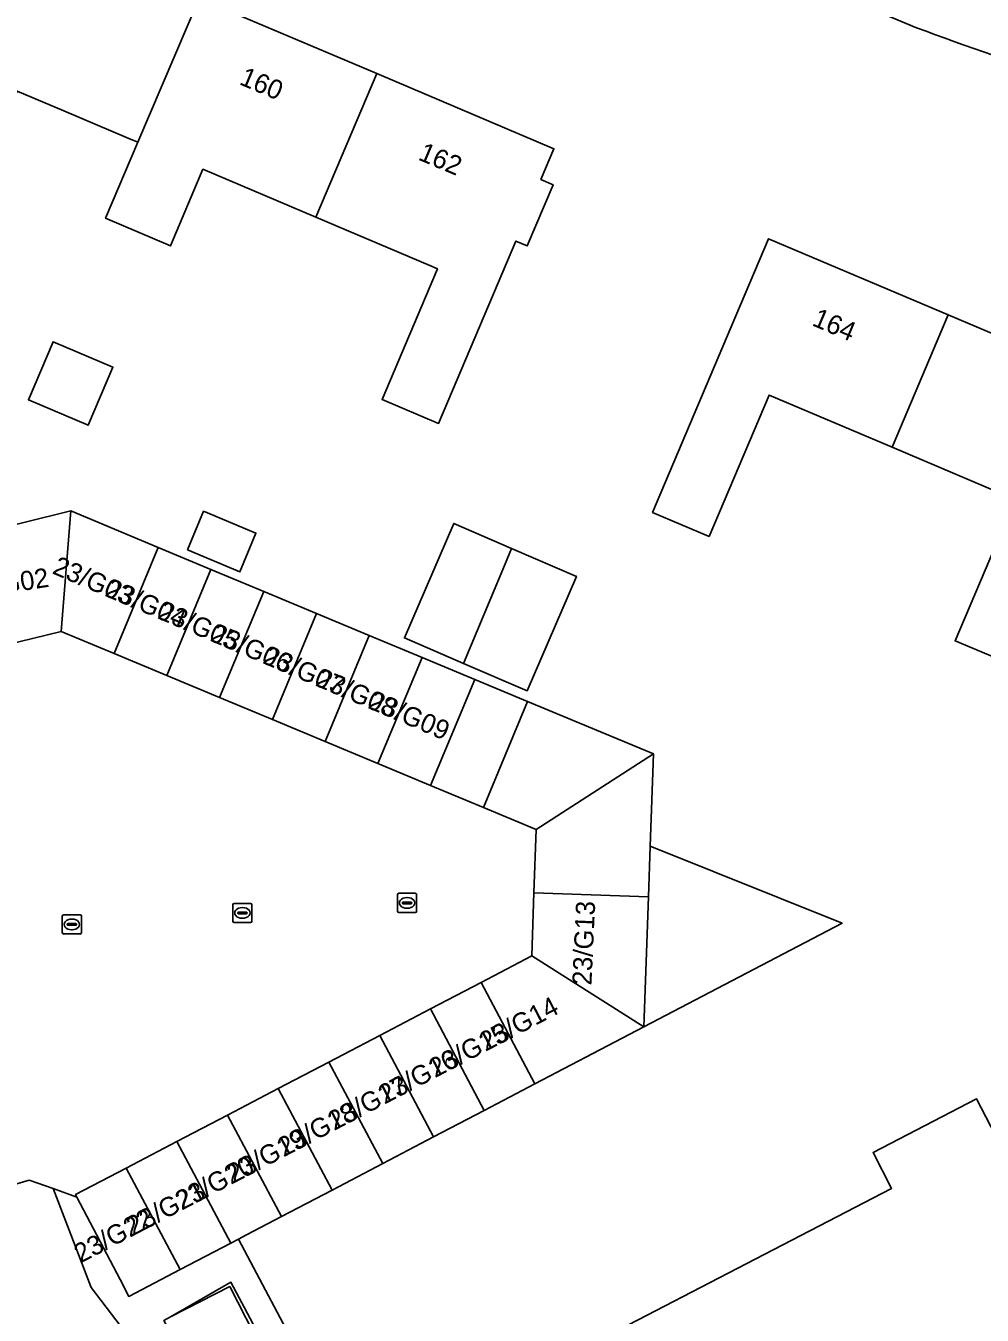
# Model space of a CAD drawing. Extents: x 162073 to 163043, y 381818 to 382561.
# Drawn here: x 162517.9 to 162567.8, y 382402.1 to 382469.3 of the extents above; entities that cross this region are included whole.
import ezdxf

# ---------------------------------------------------------------- set-up
doc = ezdxf.new("R2010")
doc.units = 0
for name, color, linetype in [('IMGEO_Erf', 7, 'Continuous'), ('IMGEO_Kolk', 7, 'Continuous'), ('IMGEO_Pand', 7, 'Continuous'), ('IMGEO_Pand_nummerreeks', 7, 'Continuous'), ('IMGEO_Rijbaan_lokaal_open', 7, 'Continuous'), ('IMGEO_Voetpad_open', 7, 'Continuous')]:
    doc.layers.add(name, color=color, linetype=linetype)

msp = doc.modelspace()

# ---------------------------------------------------------------- linework, layer by layer
at = {"layer": 'IMGEO_Erf'}
for points in [[(162564.361, 382469.237), (162500, 382496.185)], [(162526.962, 382470.776), (162536.214, 382466.853), (162545.458, 382462.933), (162544.778, 382461.328), (162545.416, 382461.057), (162544.064, 382457.868), (162543.471, 382458.119), (162539.438, 382448.608), (162536.492, 382449.857), (162539.383, 382456.674), (162538.978, 382456.846), (162533.041, 382459.363), (162527.152, 382461.86), (162525.471, 382457.865), (162522.077, 382459.304), (162523.766, 382463.272), (162523.294, 382463.472), (162519.902, 382464.91), (162517.475, 382465.939), (162517.154, 382465.181), (162513.979, 382466.527), (162515.504, 382470.123)], [(162515.42, 382442.864), (162520.267, 382444.049), (162524.823, 382442.149), (162527.574, 382441.002), (162530.326, 382439.854), (162533.078, 382438.707), (162535.83, 382437.56), (162538.581, 382436.412), (162541.333, 382435.265), (162544.085, 382434.117), (162550.649, 382431.38), (162550.479, 382426.575), (162560.476, 382422.56), (162550.145, 382417.154), (162544.462, 382414.18), (162541.819, 382412.797), (162539.176, 382411.414), (162536.533, 382410.031), (162533.89, 382408.649), (162531.247, 382407.266), (162529.419, 382406.309), (162529.011, 382406.096), (162569.932, 382328.823)], [(162570.821, 382350.911), (162559.051, 382373.589), (162560.496, 382374.339), (162558.734, 382377.733), (162557.289, 382376.983), (162555.051, 382375.822), (162551.058, 382383.517), (162553.32, 382384.692), (162545.561, 382399.659), (162563.063, 382408.737), (162562.093, 382410.607), (162567.488, 382413.404), (162568.456, 382411.534)], [(162523.393, 382400.86), (162521.332, 382403.562), (162519.34, 382408.727), (162518.098, 382409.172), (162513.191, 382407.718), (162515.105, 382401.997)], [(162531.06, 382399.243), (162528.612, 382403.839), (162525.466, 382402.043), (162528.556, 382403.617), (162529.802, 382401.169)]]:
    msp.add_lwpolyline(points, dxfattribs=at)
for points in [[(162574.703, 382448.738), (162575.327, 382448.474), (162573.959, 382445.247), (162573.328, 382445.514), (162569.311, 382436.041), (162566.374, 382437.286), (162569.496, 382444.651), (162563.083, 382447.37), (162556.671, 382450.088), (162553.548, 382442.722), (162550.601, 382443.971), (162554.7, 382453.638), (162556.651, 382458.241), (162566.01, 382454.273), (162575.368, 382450.305)], [(162518.056, 382449.845), (162519.344, 382452.87), (162522.461, 382451.542), (162521.173, 382448.518)], [(162526.347, 382442.014), (162527.188, 382444.031), (162529.921, 382442.891), (162529.08, 382440.874)], [(162544.057, 382434.671), (162540.749, 382436.096), (162537.663, 382437.426), (162540.235, 382443.395), (162543.246, 382442.097), (162546.629, 382440.64)]]:
    msp.add_lwpolyline(points, close=True, dxfattribs=at)
msp.add_arc((162613.108, 382599.454), 139.042, 249.47654, 256.46221, dxfattribs=at)
at = {"layer": 'IMGEO_Kolk'}
for p, q in [((162528.712, 382422.667), (162528.712, 382423.519)), ((162528.787, 382423.593), (162529.639, 382423.593)), ((162529.713, 382423.519), (162529.713, 382422.667)), ((162537.298, 382423.19), (162537.298, 382424.042)), ((162537.373, 382424.116), (162538.225, 382424.116)), ((162537.557, 382423.61), (162537.557, 382423.622)), ((162537.995, 382423.573), (162537.597, 382423.573)), ((162537.6, 382423.659), (162537.998, 382423.659)), ((162537.786, 382423.896), (162537.811, 382423.896)), ((162538.041, 382423.622), (162538.041, 382423.61)), ((162538.299, 382424.042), (162538.299, 382423.19)), ((162519.82, 382422.07), (162519.82, 382422.922)), ((162519.895, 382422.996), (162520.747, 382422.996)), ((162520.821, 382422.922), (162520.821, 382422.07)), ((162528.971, 382423.087), (162528.971, 382423.099)), ((162529.409, 382423.05), (162529.011, 382423.05)), ((162529.014, 382423.136), (162529.412, 382423.136)), ((162529.2, 382423.373), (162529.225, 382423.373)), ((162529.455, 382423.099), (162529.455, 382423.087)), ((162538.225, 382423.116), (162537.373, 382423.116)), ((162537.809, 382423.336), (162537.784, 382423.336)), ((162520.079, 382422.49), (162520.079, 382422.502)), ((162520.517, 382422.453), (162520.119, 382422.453)), ((162520.122, 382422.539), (162520.52, 382422.539)), ((162520.331, 382422.216), (162520.306, 382422.216)), ((162520.308, 382422.776), (162520.333, 382422.776)), ((162520.563, 382422.502), (162520.563, 382422.49)), ((162529.639, 382422.593), (162528.787, 382422.593)), ((162529.223, 382422.813), (162529.198, 382422.813)), ((162520.747, 382421.996), (162519.895, 382421.996))]:
    msp.add_line(p, q, dxfattribs=at)
for points in [[(162528.712, 382422.667), (162528.712, 382423.519)], [(162528.787, 382423.593), (162529.639, 382423.593)], [(162529.713, 382423.519), (162529.713, 382422.667)], [(162537.298, 382423.19), (162537.298, 382424.042)], [(162537.373, 382424.116), (162538.225, 382424.116)], [(162538.299, 382424.042), (162538.299, 382423.19)], [(162519.82, 382422.07), (162519.82, 382422.922)], [(162519.895, 382422.996), (162520.747, 382422.996)], [(162520.821, 382422.922), (162520.821, 382422.07)], [(162538.225, 382423.116), (162537.373, 382423.116)], [(162529.639, 382422.593), (162528.787, 382422.593)], [(162520.747, 382421.996), (162519.895, 382421.996)]]:
    msp.add_lwpolyline(points, dxfattribs=at)
for centre, radius, start, end in [((162528.789, 382423.517), 0.0765, 91.55205, 178.44795), ((162528.789, 382423.517), 0.0765, 91.55205, 178.44795), ((162529.637, 382423.517), 0.0765, 1.55205, 88.44795), ((162529.637, 382423.517), 0.0765, 1.55205, 88.44795), ((162537.375, 382424.04), 0.0765, 91.55205, 178.44795), ((162537.375, 382424.04), 0.0765, 91.55205, 178.44795), ((162537.597, 382423.619), 0.0403, 85.87752, 175.75265), ((162537.594, 382423.609), 0.0366, 178.93798, 274.71019), ((162537.998, 382423.616), 0.043, 264.86636, 352.45326), ((162538.002, 382423.621), 0.0386, 1.73085, 96.63898), ((162538.223, 382424.04), 0.0765, 1.55205, 88.44795), ((162538.223, 382424.04), 0.0765, 1.55205, 88.44795), ((162519.897, 382422.92), 0.0765, 91.55205, 178.44795), ((162519.897, 382422.92), 0.0765, 91.55205, 178.44795), ((162520.745, 382422.92), 0.0765, 1.55205, 88.44795), ((162520.745, 382422.92), 0.0765, 1.55205, 88.44795), ((162529.011, 382423.096), 0.0403, 85.87752, 175.75265), ((162529.008, 382423.086), 0.0366, 178.93798, 274.71019), ((162529.412, 382423.093), 0.043, 264.86636, 352.45326), ((162529.416, 382423.098), 0.0386, 1.73085, 96.63898), ((162537.375, 382423.192), 0.0765, 181.55205, 268.44795), ((162537.375, 382423.192), 0.0765, 181.55205, 268.44795), ((162538.223, 382423.192), 0.0765, 271.55205, 358.44795), ((162538.223, 382423.192), 0.0765, 271.55205, 358.44795), ((162520.119, 382422.499), 0.0403, 85.87752, 175.75265), ((162520.116, 382422.489), 0.0366, 178.93798, 274.71019), ((162520.52, 382422.496), 0.043, 264.86636, 352.45326), ((162520.524, 382422.501), 0.0386, 1.73085, 96.63898), ((162528.789, 382422.669), 0.0765, 181.55205, 268.44795), ((162528.789, 382422.669), 0.0765, 181.55205, 268.44795), ((162529.637, 382422.669), 0.0765, 271.55205, 358.44795), ((162529.637, 382422.669), 0.0765, 271.55205, 358.44795), ((162519.897, 382422.072), 0.0765, 181.55205, 268.44795), ((162519.897, 382422.072), 0.0765, 181.55205, 268.44795), ((162520.745, 382422.072), 0.0765, 271.55205, 358.44795), ((162520.745, 382422.072), 0.0765, 271.55205, 358.44795)]:
    msp.add_arc(centre, radius, start, end, dxfattribs=at)
for centre, major_axis, ratio, start_param, end_param in [((162537.785, 382423.616), (-0.387, 0.002), 0.722429, 4.712389, 7.853982), ((162537.81, 382423.616), (-0.39, 0.002), 0.717154, 1.570796, 4.712389), ((162529.199, 382423.093), (-0.387, 0.002), 0.722429, 4.712389, 7.853982), ((162529.224, 382423.093), (-0.39, 0.002), 0.717154, 1.570796, 4.712389), ((162520.307, 382422.496), (-0.387, 0.002), 0.722429, 4.712389, 7.853982), ((162520.332, 382422.496), (-0.39, 0.002), 0.717154, 1.570796, 4.712389)]:
    msp.add_ellipse(centre, major_axis=major_axis, ratio=ratio, start_param=start_param, end_param=end_param, dxfattribs=at)
at = {"layer": 'IMGEO_Pand'}
for points in [[(162526.962, 382470.776), (162528.109, 382473.481), (162523.506, 382475.432), (162522.33, 382472.659), (162517.456, 382474.726), (162515.504, 382470.123), (162513.979, 382466.527), (162517.154, 382465.181), (162517.475, 382465.939), (162519.902, 382464.91), (162523.294, 382463.472), (162523.766, 382463.272)], [(162536.214, 382466.853), (162526.962, 382470.776), (162523.766, 382463.272), (162522.077, 382459.304), (162525.471, 382457.865), (162527.152, 382461.86), (162533.041, 382459.363)], [(162543.471, 382458.119), (162544.064, 382457.868), (162545.416, 382461.057), (162544.778, 382461.328), (162545.458, 382462.933), (162536.214, 382466.853), (162533.041, 382459.363), (162538.978, 382456.846), (162539.383, 382456.674), (162536.492, 382449.857), (162539.438, 382448.608)], [(162563.083, 382447.37), (162566.01, 382454.273), (162556.651, 382458.241), (162554.7, 382453.638), (162550.601, 382443.971), (162553.548, 382442.722), (162556.671, 382450.088)], [(162563.083, 382447.37), (162569.496, 382444.651), (162566.374, 382437.286), (162569.311, 382436.041), (162573.328, 382445.514), (162573.959, 382445.247), (162575.327, 382448.474), (162574.703, 382448.738), (162575.368, 382450.305), (162566.01, 382454.273)], [(162522.461, 382451.542), (162519.344, 382452.87), (162518.056, 382449.845), (162521.173, 382448.518)], [(162515.42, 382442.864), (162516.84, 382437.056), (162519.767, 382437.772), (162520.267, 382444.049)], [(162522.519, 382436.625), (162524.823, 382442.149), (162520.267, 382444.049), (162519.767, 382437.772)], [(162526.347, 382442.014), (162529.08, 382440.874), (162529.921, 382442.891), (162527.188, 382444.031)], [(162543.246, 382442.097), (162540.235, 382443.395), (162537.663, 382437.426), (162540.749, 382436.096), (162542.881, 382441.212)], [(162527.574, 382441.002), (162524.823, 382442.149), (162522.519, 382436.625), (162525.271, 382435.477)], [(162543.246, 382442.097), (162542.881, 382441.212), (162540.749, 382436.096), (162544.057, 382434.671), (162546.629, 382440.64)], [(162527.574, 382441.002), (162525.271, 382435.477), (162528.022, 382434.33), (162530.326, 382439.854)], [(162530.774, 382433.182), (162533.078, 382438.707), (162530.326, 382439.854), (162528.022, 382434.33)], [(162530.774, 382433.182), (162533.526, 382432.035), (162535.83, 382437.56), (162533.078, 382438.707)], [(162535.83, 382437.56), (162533.526, 382432.035), (162536.278, 382430.887), (162538.581, 382436.412)], [(162536.278, 382430.887), (162539.029, 382429.74), (162541.333, 382435.265), (162538.581, 382436.412)], [(162541.781, 382428.592), (162544.085, 382434.117), (162541.333, 382435.265), (162539.029, 382429.74)], [(162541.781, 382428.592), (162544.533, 382427.445), (162550.649, 382431.38), (162544.085, 382434.117)], [(162550.649, 382431.38), (162544.533, 382427.445), (162544.416, 382424.15), (162550.385, 382423.938), (162550.479, 382426.575)], [(162550.479, 382426.575), (162550.385, 382423.938), (162550.145, 382417.154), (162560.476, 382422.56)], [(162550.385, 382423.938), (162544.416, 382424.15), (162544.3, 382420.854), (162550.145, 382417.154)], [(162544.3, 382420.854), (162541.657, 382419.471), (162544.462, 382414.18), (162550.145, 382417.154)], [(162544.462, 382414.18), (162541.657, 382419.471), (162539.014, 382418.089), (162541.819, 382412.797)], [(162539.176, 382411.414), (162541.819, 382412.797), (162539.014, 382418.089), (162536.371, 382416.706)], [(162539.176, 382411.414), (162536.371, 382416.706), (162533.728, 382415.323), (162536.533, 382410.031)], [(162531.085, 382413.94), (162533.89, 382408.649), (162536.533, 382410.031), (162533.728, 382415.323)], [(162531.085, 382413.94), (162528.442, 382412.558), (162531.247, 382407.266), (162533.89, 382408.649)], [(162528.442, 382412.558), (162525.799, 382411.175), (162528.604, 382405.883), (162529.011, 382406.096), (162529.419, 382406.309), (162531.247, 382407.266)], [(162525.961, 382404.5), (162528.604, 382405.883), (162525.799, 382411.175), (162523.156, 382409.792)], [(162525.961, 382404.5), (162523.156, 382409.792), (162520.514, 382408.41), (162520.581, 382408.282), (162522.832, 382403.98), (162523.291, 382403.103)], [(162525.466, 382402.043), (162525.124, 382401.848), (162526.362, 382399.418), (162529.802, 382401.169), (162528.556, 382403.617)]]:
    msp.add_lwpolyline(points, close=True, dxfattribs=at)
msp.add_lwpolyline([(162568.456, 382411.534), (162567.488, 382413.404), (162562.093, 382410.607), (162563.063, 382408.737), (162545.561, 382399.659), (162553.32, 382384.692), (162551.058, 382383.517), (162555.051, 382375.822), (162557.289, 382376.983), (162558.734, 382377.733), (162560.496, 382374.339), (162559.051, 382373.589), (162570.821, 382350.911)], dxfattribs=at)
at = {"layer": 'IMGEO_Rijbaan_lokaal_open'}
msp.add_lwpolyline([(162513.191, 382407.718), (162518.098, 382409.172), (162519.34, 382408.727), (162520.581, 382408.282), (162520.514, 382408.41), (162523.156, 382409.792), (162525.799, 382411.175), (162528.442, 382412.558), (162531.085, 382413.94), (162533.728, 382415.323), (162536.371, 382416.706), (162539.014, 382418.089), (162541.657, 382419.471), (162544.3, 382420.854), (162544.416, 382424.15), (162544.533, 382427.445), (162541.781, 382428.592), (162539.029, 382429.74), (162536.278, 382430.887), (162533.526, 382432.035), (162530.774, 382433.182), (162528.022, 382434.33), (162525.271, 382435.477), (162522.519, 382436.625), (162519.767, 382437.772), (162516.84, 382437.056)], dxfattribs=at)
at = {"layer": 'IMGEO_Voetpad_open'}
for points in [[(162483.778, 382503.442), (162492.214, 382499.445), (162500, 382496.185), (162564.361, 382469.237)], [(162569.932, 382328.823), (162529.011, 382406.096), (162528.604, 382405.883), (162525.961, 382404.5), (162523.291, 382403.103), (162522.832, 382403.98), (162520.581, 382408.282), (162519.34, 382408.727), (162521.332, 382403.562), (162523.393, 382400.86)], [(162525.466, 382402.043), (162528.612, 382403.839), (162531.06, 382399.243)]]:
    msp.add_lwpolyline(points, dxfattribs=at)
msp.add_arc((162613.108, 382599.454), 139.042, 249.47654, 256.46221, dxfattribs=at)

# ---------------------------------------------------------------- texts
at = {"layer": 'IMGEO_Pand_nummerreeks'}
for s, rotation, p in [('160', 337.1619, (162529.001, 382466.305)), ('162', 337.1619, (162538.329, 382462.376)), ('164', 337.02307, (162558.864, 382453.739)), ('23/G02', 8.74616, (162514.84, 382439.437)), ('23/G03', 336.91822, (162519.249, 382440.807)), ('23/G04', 336.91822, (162521.992, 382439.638)), ('23/G05', 336.91822, (162524.736, 382438.469)), ('23/G06', 336.91822, (162527.479, 382437.3)), ('23/G07', 336.91822, (162530.222, 382436.131)), ('23/G08', 336.91822, (162532.968, 382434.961)), ('23/G09', 336.91822, (162535.705, 382433.794)), ('23/G13', 87.35745, (162547.41, 382419.31)), ('23/G14', 27.59354, (162541.911, 382415.865)), ('23/G15', 27.59354, (162539.279, 382414.489)), ('23/G16', 27.59354, (162536.648, 382413.114)), ('23/G17', 27.59354, (162534.017, 382411.739)), ('23/G18', 27.59354, (162531.389, 382410.365)), ('23/G19', 27.59354, (162528.752, 382408.987)), ('23/G20', 27.59365, (162526.046, 382407.572)), ('23/G21', 27.59354, (162523.509, 382406.247)), ('23/G22', 27.59354, (162520.774, 382404.818))]:
    msp.add_text(s, height=1, rotation=rotation, dxfattribs=at).set_placement(p)

doc.saveas('drawing.dxf')
